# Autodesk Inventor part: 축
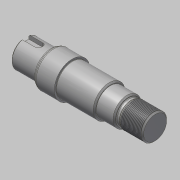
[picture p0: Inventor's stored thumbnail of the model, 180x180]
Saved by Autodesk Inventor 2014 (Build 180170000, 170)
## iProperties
Created: 2019-05
Part Number: 축
Material: 강철, 연강
Document SubType Name: Modeling
Designer: mduedu
Density: 1 g/cm^3
Appearance: 강철
Author: mduedu
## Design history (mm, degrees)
sketch "스케치1"
  geometry: L1 (0, 0)-(20, 0); L2 (20, 0)-(20, 11); L3 (20, 11)-(0, 11); L4 (0, 11)-(0, 0); L5 (20, 0)-(37, 0); L6 (37, 0)-(37, 14); L7 (37, 14)-(20, 14); L8 (20, 14)-(20, 0); L9 (37, 0)-(67, 0); L10 (67, 0)-(67, 12.5); L11 (67, 12.5)-(37, 12.5); L12 (37, 12.5)-(37, 0); L13 (67, 0)-(81, 0); L14 (81, 0)-(81, 11); L15 (81, 11)-(67, 11); L16 (67, 11)-(67, 0); L17 (81, 0)-(102, 0); L18 (102, 0)-(102, 10); L19 (102, 10)-(81, 10); L20 (81, 10)-(81, 0)
  constraints: 40 end point, 10 parallel, 5 horizontal, 5 perpendicular
  dimensions: "d0" = 102 distance between parallel lines of L18 L4; "d2" = 21 distance of L18.end L19.end; "d3" = 14 distance of L14.end L15.end; "d4" = 30 distance of L10.end L11.end; "d5" = 17 distance of L6.end L7.end; "d6" = 22 diameter of L3 L1; "d7" = 28 diameter of L7 L5; "d8" = 25 diameter of L11 L9; "d9" = 22 diameter of L15 L13; "d10" = 20 diameter of L19 L17
revolve "회전1" sketch "스케치1" stored, may be unused: angle "d11" = 90 deg
chamfer "모따기1" distance "d12" = 2.34; stored, may be unused: second distance "d13" = 2, angle "d14" = 30 deg
fillet "모깎기1" dims "d15" = 2, "d16" = 1
fillet "모깎기2" dims "d17" = 0.3
chamfer "모따기2" distance "d18" = 1; stored, may be unused: second distance "d19" = 2, angle "d20" = 30 deg
sketch "스케치2"
  geometry: L1 (102, -10)-(81, -10) reference; L2 (81, -10)-(81, -11) reference; L3 (81, -11)-(67, -11) reference; L4 (67, -11)-(67, -11.5) reference; L5 (67, -11.5)-(66, -12.5) reference; L6 (66, -12.5)-(37.3, -12.5) reference; L7 (37, -12.8)-(37, -14) reference; L8 (37, -14)-(22.876, -14) reference; L9 (21.876, -13.732)-(20.5, -12.938) reference; L10 (20, -12.072)-(20, -11) reference; L11 (20, -11)-(0, -11) reference; L12 (0, -11)-(0, 11) reference; L13 (0, 11)-(20, 11) reference; L14 (20, 11)-(20, 12.072) reference; L15 (20.5, 12.938)-(21.876, 13.732) reference; L16 (22.876, 14)-(37, 14) reference; L17 (37, 14)-(37, 12.8) reference; L18 (37.3, 12.5)-(66, 12.5) reference; L19 (66, 12.5)-(67, 11.5) reference; L20 (67, 11.5)-(67, 11) reference; L21 (67, 11)-(81, 11) reference; L22 (81, 11)-(81, 10) reference; L23 (81, 10)-(102, 10) reference; L24 (102, 10)-(102, -10) reference; L25 (0, 0)-(102, 0); L26 (81, 10)-(84.726, 10); L27 (83.34, 9.2)-(81, 9.2); L28 (81, 9.2)-(81, 10); L29 (84.726, 10)-(83.34, 9.2); A1 r 0.3 centre (37.3, -12.8) between (37.3, -12.5) and (37, -12.8) reference; A2 r 2 centre (22.876, -12) between (21.876, -13.732) and (22.876, -14) reference; A3 r 1 centre (21, -12.072) between (20, -12.072) and (20.5, -12.938) reference; A4 r 1 centre (21, 12.072) between (20.5, 12.938) and (20, 12.072) reference; A5 r 2 centre (22.876, 12) between (22.876, 14) and (21.876, 13.732) reference; A6 r 0.3 centre (37.3, 12.8) between (37, 12.8) and (37.3, 12.5) reference
  constraints: 10 end point, 1 horizontal, 1 midpoint, 1 parallel, 1 vertical
  dimensions: "d21" = 18.4 diameter of L27 L25; "d23" = 2.34 distance of L27.start L27.end; "d24" = 30 deg angle of L23 L29
revolve "회전2" sketch "스케치2" stored, may be unused: angle "d25" = 90 deg
fillet "모깎기3" dims "d26" = 0.6
chamfer "모따기3" distance "d27" = 1; stored, may be unused: second distance "d28" = 2, angle "d29" = 30 deg
feature "스레드1" dims "d30" = 10, "d31" = 0
chamfer "모따기4" distance "d32" = 1; stored, may be unused: second distance "d33" = 2, angle "d34" = 30 deg
node "작업 평면1"
sketch "스케치3"
  geometry: L1 (10, -3)-(-1, -3); L2 (-1, -3)-(-1, 3); L3 (-1, 3)-(10, 3); L4 (10, 3)-(10, -3); 3 further points
  constraints: 8 end point, 2 midpoint, 2 parallel, 1 coincident, 1 horizontal, 1 perpendicular, 1 vertical alignment, 2 other
  dimensions: "d35" = 14 dimension on L4; "d37" = 6 distance between parallel lines of L3 L1
extrude "돌출1" cut sketch "스케치3" distance "d38" = 3.5; taper "d39" = 0 deg
chamfer "모따기5" distance "d40" = 1; stored, may be unused: second distance "d41" = 2, angle "d42" = 30 deg
node "솔리드1"
node "절단 모서리 투영1"
